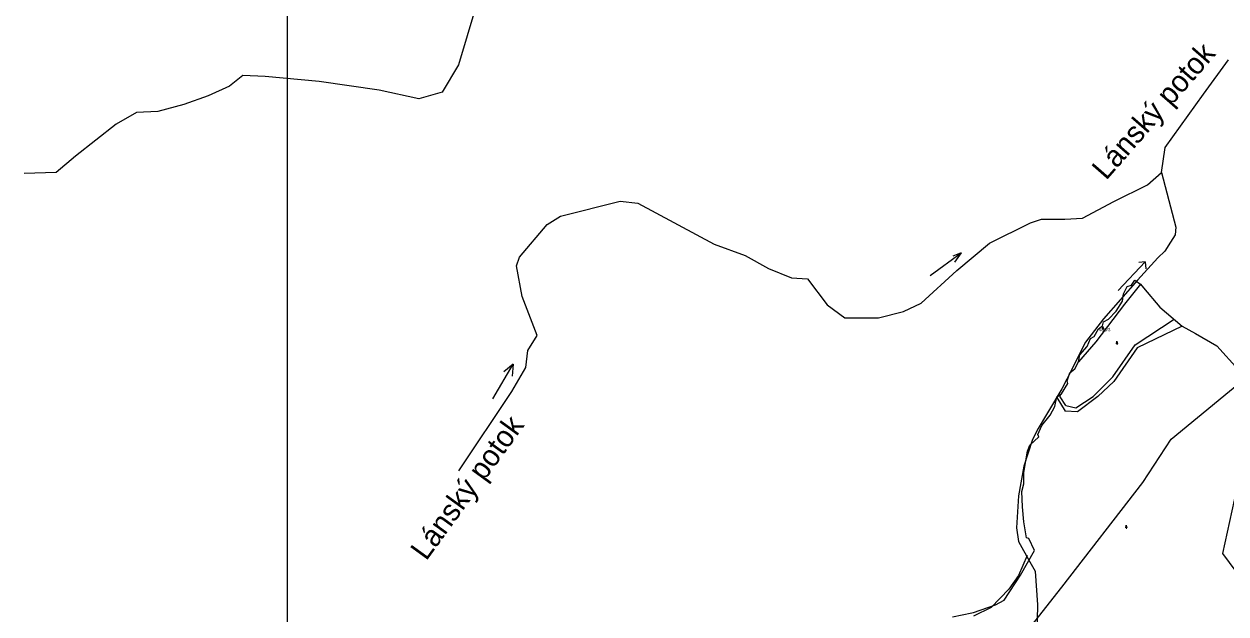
# Model space of a CAD drawing. Extents: x -564810 to -550519, y -1045831 to -1034011.
# Drawn here: x -556757 to -554954, y -1035982 to -1035097 of the extents above; entities that cross this region are included whole.
import ezdxf

# ---------------------------------------------------------------- set-up
doc = ezdxf.new("R2010")
doc.units = 0
for name, color, linetype in [('KN stav', 7, 'Continuous'), ('Názvy toků', 7, 'Continuous'), ('Parcelní čísla', 7, 'Continuous'), ('Vrstva 16', 7, 'Continuous'), ('Vrstva 33', 7, 'Continuous'), ('Vrstva 35', 7, 'Continuous'), ('Vrstva 4', 7, 'Continuous'), ('Vrstva 63', 7, 'Continuous'), ('zamokř ploch', 7, 'Continuous')]:
    doc.layers.add(name, color=color, linetype=linetype)

msp = doc.modelspace()

# ---------------------------------------------------------------- linework, layer by layer
at = {"layer": 'KN stav'}
for p, q in [((-555095.7, -1035488.2), (-555090.9, -1035480.8)), ((-555090.9, -1035480.8), (-555082.1, -1035487)), ((-555109.5, -1035512.3), (-555107.6, -1035501.5)), ((-555107.6, -1035501.5), (-555102.1, -1035490.3)), ((-555082.1, -1035487), (-555106.2, -1035516.8)), ((-555102.1, -1035490.3), (-555095.7, -1035488.2)), ((-555082.1, -1035487), (-555077.7, -1035492.2)), ((-555077.7, -1035492.2), (-555053.3, -1035521.6)), ((-555106.2, -1035516.8), (-555149.4, -1035573.6)), ((-555118.9, -1035527.4), (-555109.5, -1035512.3)), ((-555130.2, -1035539.2), (-555118.9, -1035527.4)), ((-555053.3, -1035521.6), (-555019.9, -1035549.8)), ((-555151.7, -1035565.4), (-555145.4, -1035554.1)), ((-555145.4, -1035554.1), (-555139.3, -1035549.4)), ((-555139.3, -1035549.4), (-555137.9, -1035543.2)), ((-555137.9, -1035543.2), (-555130.2, -1035539.2)), ((-555019.9, -1035549.8), (-554999.7, -1035561.1)), ((-555149.4, -1035573.6), (-555175.2, -1035603.4)), ((-555162.3, -1035580.7), (-555157.5, -1035568.5)), ((-555157.5, -1035568.5), (-555151.7, -1035565.4)), ((-554999.7, -1035561.1), (-554967.6, -1035579.7)), ((-555173.6, -1035592.8), (-555162.3, -1035580.7)), ((-554967.6, -1035579.7), (-554935.4, -1035615.5)), ((-555180.9, -1035614), (-555175.2, -1035603.4)), ((-555175.2, -1035603.4), (-555173.6, -1035592.8)), ((-555192.4, -1035632.2), (-555188.5, -1035620.2)), ((-555188.5, -1035620.2), (-555180.9, -1035614)), ((-555201.1, -1035651.5), (-555191.4, -1035636.2)), ((-555191.4, -1035636.2), (-555192.4, -1035632.2)), ((-555210.7, -1035670.5), (-555207.7, -1035656.1)), ((-555207.7, -1035656.1), (-555201.1, -1035651.5)), ((-555218.1, -1035683.4), (-555210.7, -1035670.5)), ((-555236.4, -1035712.3), (-555230.2, -1035698.8)), ((-555230.2, -1035698.8), (-555218.1, -1035683.4)), ((-555248.4, -1035728.6), (-555234.7, -1035716.2)), ((-555234.7, -1035716.2), (-555236.4, -1035712.3)), ((-555252.1, -1035737.5), (-555248.4, -1035728.6)), ((-555257.3, -1035769.4), (-555252.1, -1035737.5)), ((-555257.3, -1035786.5), (-555257.3, -1035769.4)), ((-555260.2, -1035798), (-555257.3, -1035786.5)), ((-555259.4, -1035820.9), (-555260.2, -1035798)), ((-555257.6, -1035843.5), (-555259.4, -1035820.9)), ((-555253.2, -1035867.6), (-555257.6, -1035843.5)), ((-555249.9, -1035868.4), (-555253.2, -1035867.6)), ((-555241.2, -1035886.7), (-555249.9, -1035868.4)), ((-555262.5, -1035923.4), (-555241.2, -1035886.7)), ((-555286.7, -1035960.9), (-555262.5, -1035923.4)), ((-555332.9, -1035979.3), (-555300, -1035967.9)), ((-555300, -1035967.9), (-555286.7, -1035960.9)), ((-555364.2, -1035986.2), (-555335.3, -1035979.9)), ((-555335.3, -1035979.9), (-555332.9, -1035979.3))]:
    msp.add_line(p, q, dxfattribs=at)
at = {"layer": 'Vrstva 16'}
msp.add_lwpolyline([(-556015.1, -1038013.2), (-556091.6, -1037870.1), (-556133.9, -1037708.1), (-556133.9, -1037680.7), (-556114, -1037521.2), (-555996.9, -1037316), (-555869.8, -1037156.5), (-555752.7, -1037049.3), (-555625.7, -1036867.3), (-555516, -1036650.5), (-555446.3, -1036436.1), (-555351.6, -1036199.3), (-555262.9, -1036021.1), (-555200.6, -1035941.4), (-555078.6, -1035784.3), (-555036.2, -1035719.5), (-554909.1, -1035614.8)], dxfattribs=at)
at = {"layer": 'Vrstva 33'}
for points in [[(-556079.4, -1035070.8), (-556105.5, -1035158), (-556130.2, -1035198.7), (-556165.1, -1035208.9), (-556224.7, -1035195.8), (-556314.8, -1035182.7), (-556395.6, -1035175.5), (-556429, -1035174), (-556449.3, -1035190), (-556481.3, -1035204.5), (-556517.6, -1035217.6), (-556556.9, -1035227.8), (-556588.8, -1035229.3), (-556619.4, -1035246.7), (-556680.4, -1035294.7), (-556709.4, -1035319.4), (-556757.4, -1035320.8)], [(-556105.2, -1035767.1), (-556025.4, -1035648.2), (-556004.4, -1035611.8), (-556001.7, -1035586.6), (-555987.7, -1035564.2), (-556010, -1035505.4), (-556018.4, -1035459.2), (-556014.2, -1035446.6), (-555972.3, -1035397.6), (-555952.7, -1035385), (-555863.1, -1035362.6), (-555836.6, -1035365.4), (-555721.8, -1035427), (-555675.7, -1035443.8), (-555640.7, -1035463.4), (-555605.7, -1035477.4), (-555581.9, -1035478.8), (-555552.5, -1035518), (-555525.9, -1035537.6), (-555475.6, -1035537.6), (-555437.8, -1035527.8), (-555411.2, -1035515.2), (-555358.1, -1035466.2), (-555309.1, -1035425.6), (-555247.5, -1035394.8), (-555230.7, -1035389.2), (-555195.8, -1035389.2), (-555169.2, -1035387.8), (-555122.2, -1035363), (-555071.8, -1035337.8), (-555050.8, -1035319.6), (-555045.2, -1035281.8), (-554987.9, -1035202.1), (-554950.1, -1035150.3)]]:
    msp.add_lwpolyline(points, dxfattribs=at)
at = {"layer": 'Vrstva 35'}
for p, q in [((-555351.4, -1035439.9), (-555361.5, -1035453.8)), ((-555075.5, -1035453.3), (-555074.2, -1035463.7)), ((-556023.6, -1035607.1), (-556024.9, -1035624.8))]:
    msp.add_line(p, q, dxfattribs=at)
for points in [[(-555050.8, -1035319.6), (-555037.3, -1035370.9), (-555029.4, -1035401.6), (-555030.1, -1035412.7), (-555037.3, -1035423.9), (-555045.7, -1035437.6), (-555056.2, -1035447.4), (-555086.9, -1035480.7), (-555137.8, -1035538.8), (-555164.6, -1035574.1), (-555174.4, -1035592.4), (-555184.8, -1035614), (-555200.5, -1035644), (-555222.1, -1035679.9), (-555235.8, -1035703.5), (-555244.3, -1035720), (-555257.3, -1035759.8), (-555265.2, -1035804.3), (-555268.4, -1035852.6), (-555265.2, -1035872.9), (-555248.2, -1035903.6), (-555240.3, -1035917.3), (-555237.1, -1035968.2), (-555237.7, -1036012.7)], [(-555398, -1035474), (-555351.4, -1035439.9), (-555364, -1035445)], [(-555115.9, -1035496.4), (-555075.5, -1035453.3), (-555084.6, -1035454.6)], [(-556053.9, -1035658.8), (-556023.6, -1035607.1), (-556037.5, -1035618.5)], [(-555252.4, -1035894.1), (-555265.4, -1035924.2), (-555279.8, -1035944.4), (-555306.6, -1035971.9), (-555332.7, -1035984.9)]]:
    msp.add_lwpolyline(points, dxfattribs=at)
at = {"layer": 'Vrstva 4'}
for p, q in [((-555090.1, -1035577.9), (-555031.9, -1035539.6)), ((-555019.9, -1035549.8), (-555087.2, -1035582.6)), ((-555123.6, -1035626), (-555090.1, -1035577.9)), ((-555087.2, -1035582.6), (-555122.3, -1035633)), ((-555153.3, -1035655.5), (-555123.6, -1035626)), ((-555122.3, -1035633), (-555146.1, -1035655.5)), ((-555207.9, -1035657.1), (-555195.2, -1035677.5)), ((-555203, -1035656.1), (-555202.4, -1035652.4)), ((-555194.3, -1035669.2), (-555203, -1035656.1)), ((-555179.3, -1035672.5), (-555153.3, -1035655.5)), ((-555146.1, -1035655.5), (-555177.1, -1035678.4)), ((-555177.1, -1035678.4), (-555195.2, -1035677.5)), ((-555194.3, -1035669.2), (-555179.3, -1035672.5)), ((-554913.3, -1035679.3), (-554959.2, -1035891.2)), ((-554959.2, -1035891.2), (-554921, -1035942.9))]:
    msp.add_line(p, q, dxfattribs=at)
at = {"layer": 'Vrstva 63'}
msp.add_lwpolyline([(-550519.3, -1039635.9), (-556362.3, -1039635.9), (-556362.3, -1034682.3), (-550519.3, -1034682.3)], close=True, dxfattribs=at)
at = {"layer": 'zamokř ploch'}
for points in [[(-555139.4, -1035554.3), (-555138.7, -1035550.3), (-555137.9, -1035554.3)], [(-555138.7, -1035554.6), (-555138.7, -1035554.8), (-555137.9, -1035554.8)], [(-555118.4, -1035576.3), (-555117.7, -1035572.3), (-555116.9, -1035576.3)], [(-555117.7, -1035576.6), (-555117.7, -1035576.8), (-555116.9, -1035576.8)], [(-555104.5, -1035852.3), (-555103.8, -1035848.3), (-555103, -1035852.3)], [(-555103.8, -1035852.6), (-555103.8, -1035852.8), (-555103, -1035852.8)]]:
    msp.add_lwpolyline(points, dxfattribs=at)

# ---------------------------------------------------------------- texts
at = {"layer": 'Názvy toků'}
for rotation, p in [(48.9053, (-555133.9, -1035332.2)), (54.0506, (-556154, -1035903.1))]:
    msp.add_text('Lánský potok', height=32, rotation=rotation, dxfattribs=at).set_placement(p)
at = {"layer": 'Parcelní čísla'}
msp.add_text('486/3', height=5.1, dxfattribs=at).set_placement((-555145, -1035557.6))

doc.saveas('drawing.dxf')
